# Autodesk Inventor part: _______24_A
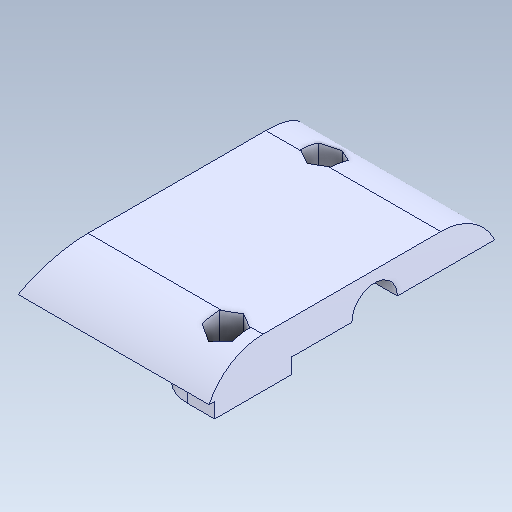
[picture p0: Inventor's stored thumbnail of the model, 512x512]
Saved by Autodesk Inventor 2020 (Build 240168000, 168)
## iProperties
Created: 2017-09
Part Number: _______24_A
Material: Générique
Document SubType Name: Modeling
Designer: bruno
Density: 1 g/cm^3
Appearance: Par défaut
Author: bruno
Sending System: SolidWorks 2016
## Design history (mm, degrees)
feature "Importée1"
node "Solide1"
